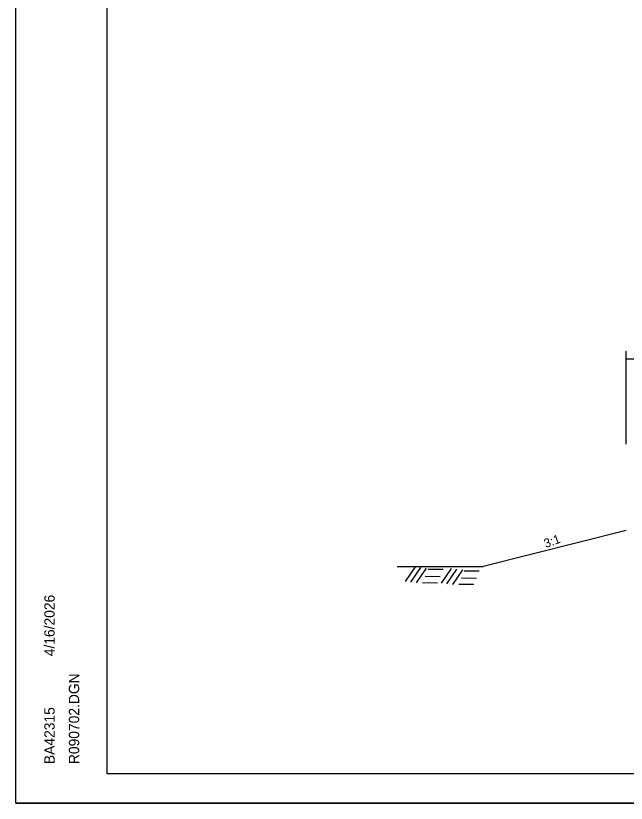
# Model space of a CAD drawing. Extents: x 1371763 to 1372860, y 385599 to 385872.
# Drawn here: x 1371763.4 to 1371804.7, y 385765.2 to 385818.5 of the extents above; entities that cross this region are included whole.
import ezdxf

# ---------------------------------------------------------------- set-up
doc = ezdxf.new("R2010")
doc.units = 0
for name, color, linetype in [('R_Draft', 7, 'Continuous'), ('R_Fin Surface', 7, 'Continuous'), ('R_No Plot', 7, 'Continuous')]:
    doc.layers.add(name, color=color, linetype=linetype)

msp = doc.modelspace()

# ---------------------------------------------------------------- linework, layer by layer
at = {"layer": 'R_Draft'}
for p, q in [((1371804.721, 385789.49), (1371804.721, 385795.788)), ((1371828.721, 385795.248), (1371804.721, 385795.248)), ((1371804.724, 385783.643), (1371795.023, 385781.218)), ((1371789.758, 385780.187), (1371790.434, 385781.188)), ((1371790.117, 385780.145), (1371790.793, 385781.146)), ((1371790.517, 385780.103), (1371791.193, 385781.105)), ((1371792.211, 385780.078), (1371792.887, 385781.08)), ((1371791.093, 385780.545), (1371792.111, 385780.537)), ((1371791.293, 385781.03), (1371792.311, 385781.021)), ((1371792.57, 385780.036), (1371793.246, 385781.038)), ((1371792.97, 385779.995), (1371793.646, 385780.996)), ((1371793.746, 385780.921), (1371794.764, 385780.913)), ((1371790.918, 385780.12), (1371791.936, 385780.112)), ((1371793.371, 385780.011), (1371794.389, 385780.003)), ((1371793.546, 385780.437), (1371794.564, 385780.429))]:
    msp.add_line(p, q, dxfattribs=at)
at = {"layer": 'R_Fin Surface'}
msp.add_line((1371789.205, 385781.218), (1371795.023, 385781.218), dxfattribs=at)
at = {"layer": 'R_No Plot'}
for p, q in [((1371769.555, 385767.168), (1371769.555, 385869.898)), ((1371769.555, 385767.168), (1371769.555, 385767.168)), ((1371927.645, 385767.168), (1371769.555, 385767.168)), ((1371763.354, 385765.179), (1371930.021, 385765.179))]:
    msp.add_line(p, q, dxfattribs=at)
for points in [[(1371763.351, 385871.845), (1371930.021, 385871.845), (1371930.021, 385765.176), (1371763.351, 385765.176)], [(1371886.515, 385869.898), (1371896.325, 385869.898), (1371896.325, 385864.958), (1371904.381, 385864.958), (1371915.98, 385864.958), (1371916.041, 385850.88), (1371927.645, 385850.88), (1371927.645, 385767.168), (1371769.555, 385767.168), (1371769.555, 385869.898)]]:
    msp.add_lwpolyline(points, close=True, dxfattribs=at)

# ---------------------------------------------------------------- texts
at = {"layer": 'R_Draft'}
msp.add_text('3:1', height=0.6, rotation=19.9978, dxfattribs=at).set_placement((1371799.264, 385782.459))
at = {"layer": 'R_No Plot'}
for s, p in [('4/16/2026', (1371765.987, 385775.132)), ('R090702.DGN', (1371767.65, 385767.83)), ('BA42315', (1371765.987, 385767.83))]:
    msp.add_text(s, height=0.7, rotation=90, dxfattribs=at).set_placement(p)

doc.saveas('drawing.dxf')
